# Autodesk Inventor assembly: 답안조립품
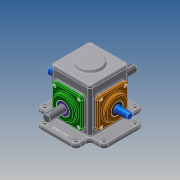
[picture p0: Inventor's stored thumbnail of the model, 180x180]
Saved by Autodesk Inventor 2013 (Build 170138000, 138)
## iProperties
Created: 2019-12
Part Number: 답안조립품
Document SubType Name: Assembly
Designer: Administrator
Mass: 3483.74 g
Surface Area: 3365.09 cm^2
Volume: 1062.39 cm^3
Density: 3.27916 g/cm^3
Author: Administrator
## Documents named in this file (16)
- C:\Users\Administrator\Documents\Inventor\391204V1030\답안조립품.iam
- C:\Users\Administrator\Documents\Inventor\391204V1030\391204V1030\개스킷.ipt
- C:\Users\Administrator\Documents\Inventor\391204V1030\391204V1030\메인베벨기어.ipt
- C:\Users\Administrator\Documents\Inventor\391204V1030\391204V1030\메인축.ipt
- C:\Users\Administrator\Documents\Inventor\391204V1030\391204V1030\메인커버.ipt
- C:\Users\Administrator\Documents\Inventor\391204V1030\391204V1030\베어링 6203.ipt
- C:\Users\Administrator\Documents\Inventor\391204V1030\391204V1030\베어링 6204.ipt
- C:\Users\Administrator\Documents\Inventor\391204V1030\391204V1030\본체.ipt
- C:\Users\Administrator\Documents\Inventor\391204V1030\391204V1030\볼트 M4.ipt
- C:\Users\Administrator\Documents\Inventor\391204V1030\391204V1030\상부커버.ipt
- C:\Users\Administrator\Documents\Inventor\391204V1030\391204V1030\서브베벨기어.ipt
- C:\Users\Administrator\Documents\Inventor\391204V1030\391204V1030\서브축.ipt
- C:\Users\Administrator\Documents\Inventor\391204V1030\391204V1030\서브커버.ipt
- C:\Users\Administrator\Documents\Inventor\391204V1030\391204V1030\오일 실 17 32 8.ipt
- C:\Users\Administrator\Documents\Inventor\391204V1030\391204V1030\오일 실 20 35 8.ipt
- C:\Users\Administrator\Documents\Inventor\391204V1030\391204V1030\키 4x4.ipt
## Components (1 placed, 1 different names)
1. 개스킷:1
